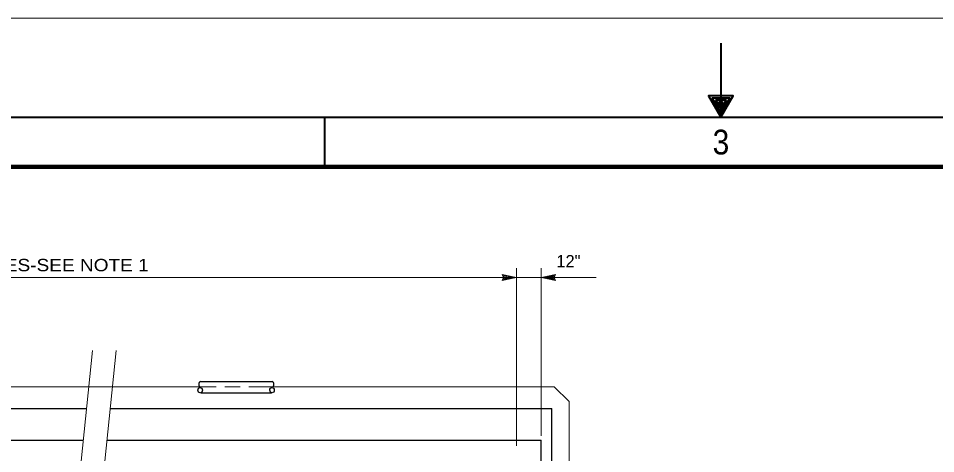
# Model space of a CAD drawing. Extents: x -24.3 to 17.7, y -17.6 to 12.4.
# Drawn here: x -10.43 to -1.17, y 7.99 to 12.39 of the extents above; entities that cross this region are included whole.
import ezdxf
from ezdxf.enums import TextEntityAlignment as Align

# ---------------------------------------------------------------- set-up
doc = ezdxf.new("R2010")
doc.units = 0
doc.header["$LTSCALE"] = 0.05
doc.layers.add('1', color=7, linetype='Continuous', lineweight=13)

msp = doc.modelspace()

# ---------------------------------------------------------------- linework, layer by layer
at = {"layer": '1', "lineweight": 40}
for p, q in [((-3.34269, 12.1394), (-3.34269, 11.3894)), ((-7.34269, 11.3894), (-7.34269, 10.8894))]:
    msp.add_line(p, q, dxfattribs=at)
at = {"layer": '1'}
for p, q in [((-5.40569, 8.0724), (-5.40569, 9.8654)), ((-5.15569, 8.1714), (-5.15569, 9.8654)), ((-12.46869, 9.7704), (-5.40569, 9.7704)), ((-5.40569, 9.7704), (-5.54969, 9.8014)), ((-5.40569, 9.7704), (-5.54969, 9.7394)), ((-5.44269, 9.7704), (-5.53669, 9.7904)), ((-5.52769, 9.7704), (-5.53669, 9.7904)), ((-5.44269, 9.7704), (-5.53669, 9.7504)), ((-5.53669, 9.7504), (-5.52769, 9.7704)), ((-5.47869, 9.7704), (-5.52369, 9.7794)), ((-5.51969, 9.7704), (-5.52369, 9.7794)), ((-5.47869, 9.7704), (-5.52369, 9.7604)), ((-5.52369, 9.7604), (-5.51969, 9.7704)), ((-5.15569, 9.7704), (-5.01169, 9.8014)), ((-5.15569, 9.7704), (-5.01169, 9.7394)), ((-5.11869, 9.7704), (-5.02469, 9.7904)), ((-5.11869, 9.7704), (-5.02469, 9.7504)), ((-5.08269, 9.7704), (-5.03769, 9.7804)), ((-5.08269, 9.7704), (-5.03769, 9.7614)), ((-5.03769, 9.7804), (-5.04169, 9.7704)), ((-5.04169, 9.7704), (-5.03769, 9.7614)), ((-5.02469, 9.7904), (-5.03369, 9.7704)), ((-5.03369, 9.7704), (-5.02469, 9.7504)), ((-9.93669, 6.5824), (-9.68569, 9.0354)), ((-9.69669, 6.5824), (-9.44569, 9.0354)), ((-12.77069, 8.6664), (-8.43669, 8.6664)), ((-8.35069, 8.6664), (-8.19369, 8.6664)), ((-8.10769, 8.6664), (-5.02569, 8.6664)), ((-4.87569, 8.5174), (-5.02569, 8.6664))]:
    msp.add_line(p, q, dxfattribs=at)
at = {"layer": '1', "lineweight": 25}
for p, q in [((-8.59669, 8.7224), (-7.87069, 8.7224)), ((-8.59069, 8.6074), (-7.87869, 8.6074)), ((-18.37569, 8.4474), (-9.74369, 8.4474)), ((-9.50569, 8.4474), (-5.05069, 8.4474)), ((-5.05069, 1.0934), (-5.05069, 8.4474)), ((-18.37569, 8.1284), (-9.77669, 8.1284)), ((-9.53869, 8.1284), (-5.15569, 8.1284)), ((-5.15569, 1.3644), (-5.15569, 8.1284))]:
    msp.add_line(p, q, dxfattribs=at)
at = {"layer": '1'}
for points in [[(-24.34269, 12.3894), (17.65731, 12.3894), (17.65731, -17.6106)], [(-5.54969, 9.7394), (-5.53569, 9.7704), (-5.54969, 9.8014)], [(-5.40569, 9.7704), (-5.15569, 9.7704), (-4.60069, 9.7704)], [(-5.01169, 9.8014), (-5.02569, 9.7704), (-5.01169, 9.7394)], [(-4.87569, 5.0674), (-4.87569, 5.9694), (-4.87569, 8.5174)]]:
    msp.add_lwpolyline(points, dxfattribs=at)
at = {"layer": '1', "lineweight": 40}
for points in [[(-3.34269, 11.3894), (-3.21769, 11.6054), (-3.46769, 11.6054)], [(-23.34269, -16.6106), (-23.34269, 11.3894), (16.65731, 11.3894), (16.65731, -16.6106)]]:
    msp.add_lwpolyline(points, close=True, dxfattribs=at)
for points in [[(-3.34169, 11.4324), (-3.25269, 11.5844), (-3.43069, 11.5844), (-3.34269, 11.4324)], [(-3.34269, 11.4714), (-3.28969, 11.5644), (-3.39469, 11.5644), (-3.34069, 11.4704)], [(-3.34269, 11.5134), (-3.32569, 11.5434), (-3.35869, 11.5434), (-3.34369, 11.5174)]]:
    msp.add_lwpolyline(points, dxfattribs=at)
at = {"layer": '1', "lineweight": 90}
msp.add_lwpolyline([(-21.84269, 10.8894), (16.15731, 10.8894), (16.15731, -16.1106), (-21.84269, -16.1106)], close=True, dxfattribs=at)
at = {"layer": '1', "lineweight": 25}
for centre, start, end in [((-8.57563, 8.69068), 123.5916, 232.71318), ((-7.89175, 8.69068), 307.28682, 56.4084)]:
    msp.add_arc(centre, 0.03807, start, end, dxfattribs=at)
for centre in [(-8.59919, 8.6334), (-7.87319, 8.6334)]:
    msp.add_ellipse(centre, major_axis=(-0.0005, 0.027), ratio=0.833928, dxfattribs=at)

# ---------------------------------------------------------------- texts
at = {"layer": '1', "width": 0.9}
msp.add_text('3', height=0.25, dxfattribs=at).set_placement((-3.34219, 11.0144), align=Align.CENTER)
at = {"layer": '1'}
msp.add_text('12"', height=0.125, dxfattribs=at).set_placement((-5.00469, 9.8734))
at = {"layer": '1', "width": 1.15}
msp.add_text('LENGTH VARIES-SEE NOTE 1', height=0.125, dxfattribs=at).set_placement((-11.85269, 9.8344))

doc.saveas('drawing.dxf')
